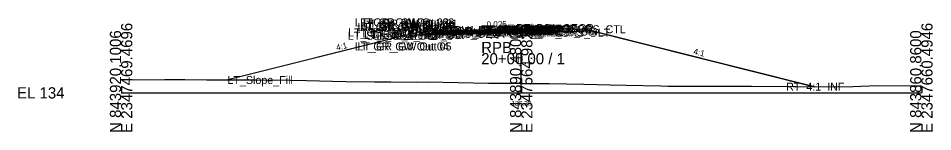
# Model space of a CAD drawing. Extents: x -76 to 2347760, y -10 to 844216.
# Drawn here: x -25.7 to 202.8, y 4990.3 to 5018.6 of the extents above; entities that cross this region are included whole.
import ezdxf

# ---------------------------------------------------------------- set-up
doc = ezdxf.new("R2010")
doc.units = 0
for name, color, linetype in [('Default', 7, 'Continuous'), ('Exist Cross Section Cell', 7, 'Continuous'), ('Exist XS Center Line Elevation Label', 7, 'Continuous'), ('Exist XS Ground Line', 7, 'Continuous'), ('Prop CMT Pvmt Course 1', 7, 'Continuous'), ('Prop CMT Pvmt Course 2', 7, 'Continuous'), ('Prop CMT Pvmt Course 3', 7, 'Continuous'), ('Prop CMT Pvmt Surface', 7, 'Continuous'), ('Prop CMT Pvmt Surface Shoulder', 7, 'Continuous'), ('Prop CMT Shld Paved Course 1', 7, 'Continuous'), ('Prop CMT Shld Paved Course 2', 7, 'Continuous'), ('Prop CMT Shld Paved Course 3', 7, 'Continuous'), ('Prop CMT Slope Grass', 7, 'Continuous'), ('Prop CMT Subgrade Earthwork', 7, 'Continuous'), ('Prop XS Earthwork Shape', 7, 'Continuous'), ('Prop XS SE Text', 7, 'Continuous'), ('Prop XS Side Slope Text', 7, 'Continuous'), ('Scratch_Level_0', 7, 'Continuous')]:
    doc.layers.add(name, color=color, linetype=linetype)

msp = doc.modelspace()

# ---------------------------------------------------------------- linework, layer by layer
at = {"layer": 'Exist Cross Section Cell'}
for p, q in [((100, 5000), (100, 5009.92)), ((0, 5000), (100, 5000)), ((100, 5000), (200, 5000))]:
    msp.add_line(p, q, dxfattribs=at)
at = {"layer": 'Exist XS Ground Line'}
msp.add_lwpolyline([(0, 5003.31), (0.78, 5003.29), (10.96, 5003.3), (15.95, 5003.3), (21.43, 5003.28), (31.13, 5003.23), (31.9, 5003.23), (33.62, 5003.22), (42.37, 5003.14), (46.31, 5003.05), (52.84, 5002.91), (56.29, 5002.85), (63.31, 5002.79), (67.38, 5002.78), (73.78, 5002.7), (76.66, 5002.73), (84.25, 5002.6), (91.84, 5002.46), (94.72, 5002.42), (100, 5002.38), (101.15, 5002.37), (105.19, 5002.33), (107.01, 5002.31), (115.66, 5002.21), (122.19, 5001.99), (126.13, 5001.9), (134.91, 5001.73), (136.6, 5001.71), (137.37, 5001.7), (147.07, 5001.65), (152.54, 5001.68), (157.54, 5001.67), (168.01, 5001.6), (168.67, 5001.59), (178.48, 5001.47), (182.9, 5001.58), (188.95, 5001.81), (198.07, 5001.74), (199.43, 5001.77), (200, 5001.78)], dxfattribs=at)
at = {"layer": 'Prop CMT Pvmt Course 1'}
for p, q in [((100, 5015.95), (88, 5015.65)), ((88, 5015.4), (100, 5015.7)), ((88, 5015.65), (88, 5015.4)), ((100, 5015.95), (104, 5016.05)), ((100, 5015.7), (100, 5015.95)), ((100, 5015.7), (100, 5015.95)), ((100, 5015.7), (100, 5015.82)), ((100, 5015.82), (100, 5015.82)), ((100, 5015.82), (100, 5015.7)), ((100, 5015.7), (100, 5015.82)), ((100, 5015.82), (100, 5015.82)), ((100, 5015.82), (100, 5015.7)), ((104, 5015.8), (100, 5015.7)), ((100, 5015.7), (100, 5015.7)), ((100, 5015.7), (100, 5015.7)), ((104, 5016.05), (104, 5015.8))]:
    msp.add_line(p, q, dxfattribs=at)
at = {"layer": 'Prop CMT Pvmt Course 2'}
for p, q in [((100, 5015.7), (88, 5015.4)), ((88, 5015.4), (88, 5015.07)), ((88, 5015.07), (100, 5015.37)), ((100, 5015.7), (104, 5015.8)), ((100, 5015.37), (100, 5015.7)), ((100, 5015.37), (100, 5015.7)), ((104, 5015.47), (100, 5015.37)), ((104, 5015.8), (104, 5015.47))]:
    msp.add_line(p, q, dxfattribs=at)
at = {"layer": 'Prop CMT Pvmt Course 3'}
for p, q in [((100, 5015.37), (88, 5015.07)), ((88, 5015.07), (88, 5014.73)), ((88, 5014.73), (100, 5015.03)), ((100, 5015.37), (104, 5015.47)), ((100, 5015.03), (100, 5015.37)), ((100, 5015.03), (100, 5015.37)), ((104, 5015.13), (100, 5015.03)), ((104, 5015.47), (104, 5015.13))]:
    msp.add_line(p, q, dxfattribs=at)
at = {"layer": 'Prop CMT Pvmt Surface'}
for q in [(88, 5015.65), (104, 5016.05)]:
    msp.add_line((100, 5015.95), q, dxfattribs=at)
at = {"layer": 'Prop CMT Pvmt Surface Shoulder'}
for p, q in [((88, 5015.65), (78, 5015.4)), ((104, 5016.05), (108, 5016.15))]:
    msp.add_line(p, q, dxfattribs=at)
at = {"layer": 'Prop CMT Shld Paved Course 1'}
for p, q in [((78, 5015.4), (77.74, 5015.14)), ((77.74, 5015.14), (88, 5015.4)), ((88, 5015.65), (78, 5015.4)), ((88, 5015.4), (88, 5015.65)), ((104, 5016.05), (108, 5016.15)), ((104, 5015.8), (104, 5016.05)), ((108.24, 5015.9), (104, 5015.8)), ((108, 5016.15), (108.24, 5015.9))]:
    msp.add_line(p, q, dxfattribs=at)
at = {"layer": 'Prop CMT Shld Paved Course 2'}
for p, q in [((77.74, 5015.14), (77.4, 5014.8)), ((77.4, 5014.8), (88, 5015.07)), ((88, 5015.4), (77.74, 5015.14)), ((88, 5015.07), (88, 5015.4)), ((104, 5015.8), (108.24, 5015.9)), ((104, 5015.47), (104, 5015.8)), ((108.57, 5015.58), (104, 5015.47)), ((108.24, 5015.9), (108.57, 5015.58))]:
    msp.add_line(p, q, dxfattribs=at)
at = {"layer": 'Prop CMT Shld Paved Course 3'}
for p, q in [((76.9, 5014.79), (76.56, 5014.45)), ((76.56, 5014.45), (88, 5014.73)), ((77.4, 5014.8), (76.9, 5014.79)), ((88, 5015.07), (77.4, 5014.8)), ((88, 5014.73), (88, 5015.07)), ((104, 5015.47), (108.57, 5015.58)), ((104, 5015.13), (104, 5015.47)), ((109.39, 5015.27), (104, 5015.13)), ((108.57, 5015.58), (109.07, 5015.59)), ((109.07, 5015.59), (109.39, 5015.27))]:
    msp.add_line(p, q, dxfattribs=at)
at = {"layer": 'Prop CMT Slope Grass'}
for p, q in [((74, 5015.08), (26.7, 5003.25)), ((78, 5015.4), (74, 5015.08)), ((108, 5016.15), (116, 5015.87)), ((116, 5015.87), (173.33, 5001.54))]:
    msp.add_line(p, q, dxfattribs=at)
at = {"layer": 'Prop CMT Subgrade Earthwork'}
for p, q in [((76.56, 5014.45), (70.9, 5014.3)), ((88, 5014.73), (76.56, 5014.45)), ((100, 5015.03), (88, 5014.73)), ((100, 5015.03), (104, 5015.13)), ((104, 5015.13), (117.59, 5015.47))]:
    msp.add_line(p, q, dxfattribs=at)
at = {"layer": 'Prop XS Earthwork Shape'}
msp.add_lwpolyline([(100, 5015.03), (88, 5014.73), (76.56, 5014.45), (70.9, 5014.3), (26.7, 5003.25), (31.13, 5003.23), (31.9, 5003.23), (33.62, 5003.22), (42.37, 5003.14), (46.31, 5003.05), (52.84, 5002.91), (56.29, 5002.85), (63.31, 5002.79), (67.38, 5002.78), (73.78, 5002.7), (76.66, 5002.73), (84.25, 5002.6), (91.84, 5002.46), (94.72, 5002.42), (100, 5002.38), (101.15, 5002.37), (105.19, 5002.33), (107.01, 5002.31), (115.66, 5002.21), (122.19, 5001.99), (126.13, 5001.9), (134.91, 5001.73), (136.6, 5001.71), (137.37, 5001.7), (147.07, 5001.65), (152.54, 5001.68), (157.54, 5001.67), (168.01, 5001.6), (168.67, 5001.59), (173.33, 5001.54), (117.59, 5015.47), (104, 5015.13)], close=True, dxfattribs=at)

# ---------------------------------------------------------------- texts
at = {"layer": 'Default'}
msp.add_text('-', height=0.0001, dxfattribs=at).set_placement((0, 5000))
at = {"layer": 'Exist Cross Section Cell'}
for s, p in [('E 2347469.4696', (2.8, 4990)), ('E 2347564.9821', (102.8, 4990)), ('E 2347660.4946', (202.8, 4990)), ('N 843920.1006', (0, 4990)), ('N 843890.4803', (100, 4990)), ('N 843860.8600', (200, 4990))]:
    msp.add_text(s, height=2.8, rotation=90, dxfattribs=at).set_placement(p)
for s, p in [('RPB', (90, 5009.92)), ('20+00.00 / 1', (90, 5007.12)), ('EL 134', (-26, 4998.6))]:
    msp.add_text(s, height=2.8, dxfattribs=at).set_placement(p)
at = {"layer": 'Exist XS Center Line Elevation Label'}
msp.add_text('136.38', height=1.2, dxfattribs=at).set_placement((97.52, 4996.78))
at = {"layer": 'Prop XS SE Text'}
msp.add_text('0.025', height=1.5, rotation=1.4321, dxfattribs=at).set_placement((91.38, 5016.31))
at = {"layer": 'Prop XS Side Slope Text'}
for rotation, p in [(14.0362, (53.93, 5010.52)), (345.9638, (142.94, 5009.69))]:
    msp.add_text('4:1', height=1.5, rotation=rotation, dxfattribs=at).set_placement(p)
at = {"layer": 'Scratch_Level_0'}
for s, p in [('LT_GR_GW Out 03', (58.43, 5016.58)), ('LT_GR_GW Out 02', (59.77, 5016.58)), ('LT_GR_GW Out 06', (59.05, 5015.41)), ('LT_GR_GW Out 09', (59.77, 5015.99)), ('LT_GR_GW Out 07', (59.77, 5015.41)), ('LT_GR_GW Out 08', (60.04, 5015.7)), ('LT_GR_GW Out 01', (60.6, 5016.29)), ('LT_PS1_OEOP', (68.8, 5014.4)), ('LT_PV2_OEOT', (78.17, 5014.4)), ('LT_PV1_OEOT', (78.74, 5014.65)), ('RT_PV2_OEEOP', (89.26, 5014.7)), ('RT_PV3_OEEOP', (89.26, 5014.37)), ('LT_PV2_OEEOP', (89.31, 5014.7)), ('LT_PV3_OEEOP', (89.31, 5014.37)), ('RT_PV1_OEEOP', (89.83, 5014.82)), ('LT_PV1_OEEOP', (89.87, 5014.82)), ('RT_PV2_IEEOP', (89.91, 5014.7)), ('LT_PV2_IEEOP', (89.95, 5014.7)), ('RT_PV1_IEEOP', (90.47, 5014.82)), ('LT_PV1_IEEOP', (90.52, 5014.82)), ('RT_Sub_Trench_Out', (93.55, 5014.27)), ('PV2_PGL', (93.91, 5014.7)), ('RT_PV2_OEOT', (94.13, 5014.8)), ('RT_PV3_OEOT', (94.13, 5014.47)), ('PV1_PGL', (94.47, 5014.95)), ('RT_PV1_OEOT', (94.69, 5015.05)), ('RT_PS3_Shelf_Out', (95.01, 5014.59)), ('RT_PS2_OEOP', (98.43, 5014.9)), ('RT_PS1_OEOP', (98.76, 5015.15)), ('RT_PS3_OEOP', (98.76, 5014.58)), ('RT_GS_OS_CTL', (105.32, 5014.87)), ('LT_Sub_OSS_DLT', (56.67, 5013.26)), ('LT_GS_OS_GR_Face_GW', (56.75, 5014.08)), ('LT_GS_OS_CTL', (60.36, 5013.84)), ('LT_Sub_Trench_Out', (60.76, 5013.45)), ('LT_PS3_Shelf_Out', (62.89, 5013.79)), ('LT_PS3_OEOP', (67.64, 5013.8)), ('LT_PS2_OEOP', (67.98, 5014.14)), ('LT_Sub_OEOT', (78.08, 5013.73)), ('LT_PV3_OEOT', (78.17, 5014.07)), ('RT_Sub_OEEOP', (89.17, 5014.03)), ('LT_Sub_OEEOP', (89.21, 5014.03)), ('RT_Sub_OEOT', (94.03, 5014.13)), ('RT_Sub_OSS_DLT', (98.75, 5014.01)), ('LT_GR_GW Out 04', (58.43, 5010.58)), ('LT_GR_GW Out 05', (59.1, 5010.58)), ('LT_Slope_Fill', (26.58, 5002.2)), ('RT_4:1_INF', (166.21, 5000.54))]:
    msp.add_text(s, height=2, dxfattribs=at).set_placement(p)

doc.saveas('drawing.dxf')
